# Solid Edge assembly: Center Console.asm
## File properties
Author: m_hel
Template: iso metric assembly.asm
Last saved by: m_hel
Revision: 16
Application: Solid Edge
Username: m_hel
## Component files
Console.par
Wheel Cover.par
wheel.par
Throttle Lever.par
Console Lid.psm
Console Lid Frame.psm
Throttle Lever Body.par
Lid Handle.asm
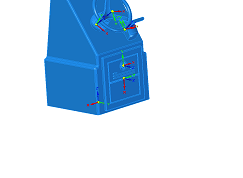
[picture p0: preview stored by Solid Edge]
